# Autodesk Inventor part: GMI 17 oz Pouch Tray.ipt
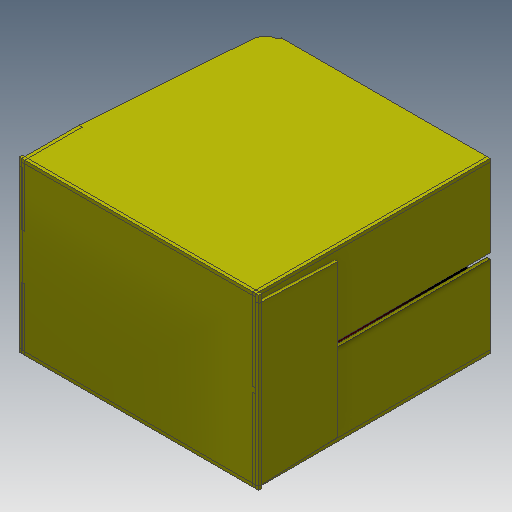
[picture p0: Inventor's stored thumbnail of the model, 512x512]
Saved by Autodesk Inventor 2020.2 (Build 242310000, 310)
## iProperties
Created: 2019-12
Part Number: GMI 17 oz Pouch Tray.ipt
Material: 1.0501 C35
Document SubType Name: Modeling
Designer: lutzd
Mass: 570.322 g
Surface Area: 3951.57 cm^2
Volume: 570.322 cm^3
Density: 7.84 g/cm^3
Appearance: Stahl
VLDS_Profile: Default Part
VLDS_TimeStamp: 2016-07-29
VLDS_FailCnt: 0
VLDS_AcceptCnt: 0
Dimensions: 159x220,5x225,5 mm
Mass: 0,57 kg
DocNumber: GMI 17 oz Pouch Tray.ipt
Folder: 01 - Themengebiete\Simplification\01 - Packaging machine\Parts\
VDS_Category: 3D Komponenten
VDS_NumSchm: Kein
VLT_Material: 1.0501 C35
Title: GMI 17 oz Pouch Tray
Author: lutzd
Revision Number: -
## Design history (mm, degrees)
derived "GMI 17 oz Pouch Tray.iam"
node "Volumenkörper1"
node "ADSK-011828.ipt:1"
node "ADSK-011829.ipt:1"
node "Volumenkörper2"
node "ADSK-011831.ipt:1"
node "Volumenkörper3"
node "ADSK-011832.ipt:1"
node "Volumenkörper4"
node "ADSK-011837.ipt:1"
node "Volumenkörper5"
node "ADSK-011837.ipt:2"
node "Volumenkörper6"
node "ADSK-011838.ipt:1"
node "Volumenkörper7"
node "ADSK-011838.ipt:2"
node "Volumenkörper8"
node "ADSK-011831.ipt:2"
node "Volumenkörper9"
node "ADSK-011830.ipt:1"
node "Volumenkörper10"
node "ADSK-011830.ipt:2"
node "Volumenkörper11"
node "ADSK-011830.ipt:3"
node "Volumenkörper12"
node "ADSK-011830.ipt:4"
node "Volumenkörper13"
node "ADSK-011830.ipt:5"
node "Volumenkörper14"
node "ADSK-011830.ipt:6"
node "Volumenkörper15"
